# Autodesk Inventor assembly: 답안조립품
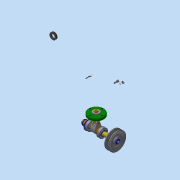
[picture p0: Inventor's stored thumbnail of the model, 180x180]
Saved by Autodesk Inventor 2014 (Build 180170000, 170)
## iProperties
Created: 2016-08
Part Number: 답안조립품
Document SubType Name: Assembly
Designer: 703-04
Author: 703-04
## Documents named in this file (25)
- C:\Users\703-04\Desktop\460808V1021\답안조립품.iam
- C:\Users\703-04\Desktop\460808V1021\본체.ipt
- C:\Users\703-04\Desktop\460808V1021\V-벨트풀리.ipt
- C:\Users\703-04\Desktop\460808V1021\너트 M10.ipt
- C:\Users\703-04\Desktop\460808V1021\링크.ipt
- C:\Users\703-04\Desktop\460808V1021\멈춤링 15 x 1.ipt
- C:\Users\703-04\Desktop\460808V1021\멈춤링 35x1.6.ipt
- C:\Users\703-04\Desktop\460808V1021\베어링 15 x 35 x 11.ipt
- C:\Users\703-04\Desktop\460808V1021\볼트 M4 x 10.ipt
- C:\Users\703-04\Desktop\460808V1021\볼트 M4 x 12.ipt
- C:\Users\703-04\Desktop\460808V1021\부시1.ipt
- C:\Users\703-04\Desktop\460808V1021\부시2.ipt
- C:\Users\703-04\Desktop\460808V1021\분할핀 1.6 x 12.ipt
- C:\Users\703-04\Desktop\460808V1021\사이드 커버.ipt
- 사이드 커버.ipt
- C:\Users\703-04\Desktop\460808V1021\슬라이더.ipt
- C:\Users\703-04\Desktop\460808V1021\오일 실 15 25 7.ipt
- C:\Users\703-04\Desktop\460808V1021\와셔 4x16.ipt
- C:\Users\703-04\Desktop\460808V1021\와셔 10x21.ipt
- C:\Users\703-04\Desktop\460808V1021\클래스터 핀 6 x 24.ipt
- C:\Users\703-04\Desktop\460808V1021\키 4 x 4 x 18.ipt
- C:\Users\703-04\Desktop\460808V1021\탑 부시.ipt
- C:\Users\703-04\Desktop\460808V1021\탑 커버.ipt
- 탑 커버.ipt
- C:\Users\703-04\Desktop\460808V1021\편심축.ipt
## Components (3 placed, 3 different names)
1. V-벨트풀리:1
2. ISO 4017 M4 x 10:1
3. ISO 4762 M4 x 12:1
